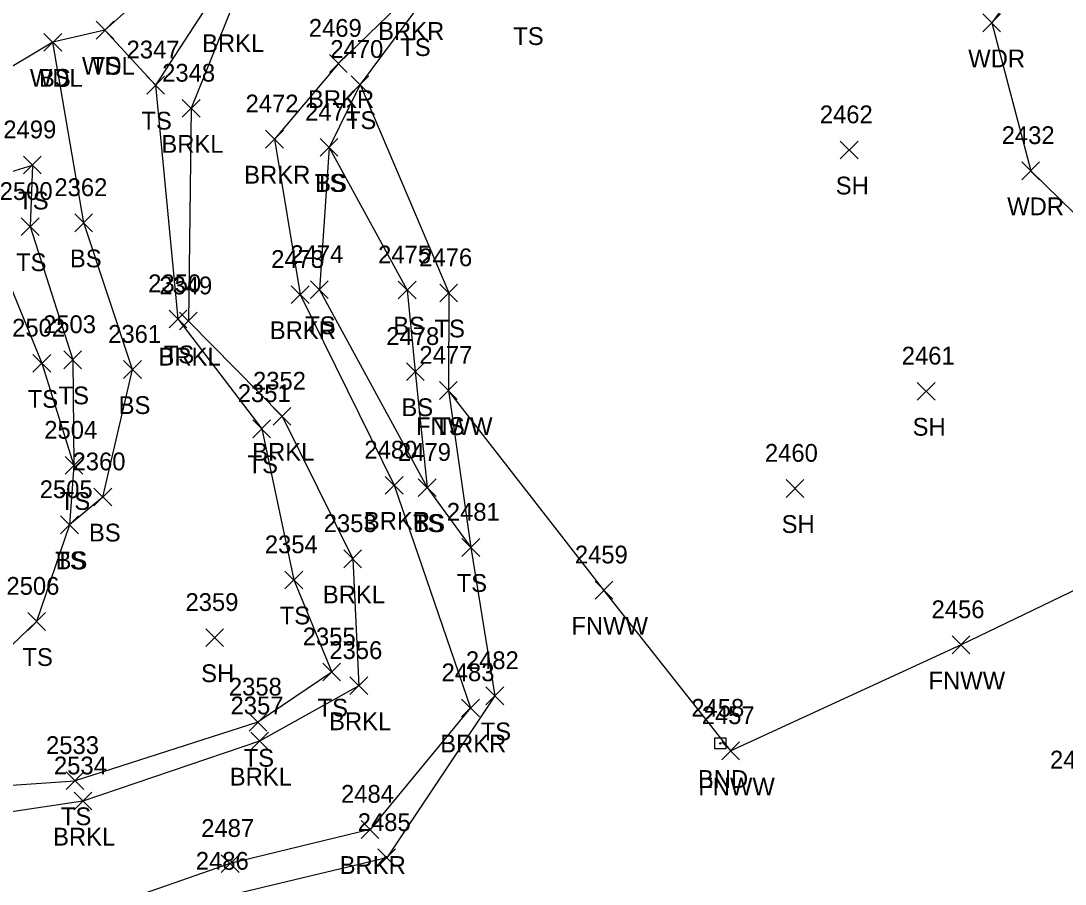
# Model space of a CAD drawing. Extents: x 1505656 to 1508446, y 700805 to 703031.
# Drawn here: x 1506706.6 to 1506823.9, y 702094.5 to 702191.5 of the extents above; entities that cross this region are included whole.
import ezdxf

# ---------------------------------------------------------------- set-up
doc = ezdxf.new("R2010")
doc.units = 0
for name, color, linetype in [('L_A', 7, 'Continuous'), ('L_I', 7, 'Continuous'), ('L_TIC', 7, 'Continuous'), ('LAWA', 7, 'Continuous'), ('LAWE', 7, 'Continuous'), ('LELB', 7, 'Continuous'), ('Level 18', 7, 'Continuous'), ('LFNC', 7, 'Continuous'), ('M_A', 7, 'Continuous'), ('M_I', 7, 'Continuous')]:
    doc.layers.add(name, color=color, linetype=linetype)

msp = doc.modelspace()

# ---------------------------------------------------------------- linework, layer by layer
at = {"layer": 'L_TIC'}
for points in [[(1506814.67, 702190.31), (1506816.67, 702192.31)], [(1506816.67, 702190.31), (1506814.67, 702192.31)], [(1506715.01, 702189.48), (1506717.01, 702191.48)], [(1506717.01, 702189.48), (1506715.01, 702191.48)], [(1506715.01, 702189.48), (1506717.01, 702191.48)], [(1506717.01, 702189.48), (1506715.01, 702191.48)], [(1506709.15, 702188.12), (1506711.15, 702190.12)], [(1506711.15, 702188.12), (1506709.15, 702190.12)], [(1506709.15, 702188.12), (1506711.15, 702190.12)], [(1506711.15, 702188.12), (1506709.15, 702190.12)], [(1506741.24, 702185.74), (1506743.24, 702187.74)], [(1506743.24, 702185.74), (1506741.24, 702187.74)], [(1506720.7, 702183.31), (1506722.7, 702185.31)], [(1506722.7, 702183.31), (1506720.7, 702185.31)], [(1506720.7, 702183.31), (1506722.7, 702185.31)], [(1506722.7, 702183.31), (1506720.7, 702185.31)], [(1506743.68, 702183.37), (1506745.68, 702185.37)], [(1506745.68, 702183.37), (1506743.68, 702185.37)], [(1506743.68, 702183.37), (1506745.68, 702185.37)], [(1506745.68, 702183.37), (1506743.68, 702185.37)], [(1506724.7, 702180.7), (1506726.7, 702182.7)], [(1506726.7, 702180.7), (1506724.7, 702182.7)], [(1506734.07, 702177.24), (1506736.07, 702179.24)], [(1506736.07, 702177.24), (1506734.07, 702179.24)], [(1506740.2, 702176.31), (1506742.2, 702178.31)], [(1506742.2, 702176.31), (1506740.2, 702178.31)], [(1506740.2, 702176.31), (1506742.2, 702178.31)], [(1506742.2, 702176.31), (1506740.2, 702178.31)], [(1506798.65, 702176.02), (1506800.65, 702178.02)], [(1506800.65, 702176.02), (1506798.65, 702178.02)], [(1506706.86, 702174.33), (1506708.86, 702176.33)], [(1506708.86, 702174.33), (1506706.86, 702176.33)], [(1506819.05, 702173.68), (1506821.05, 702175.68)], [(1506821.05, 702173.68), (1506819.05, 702175.68)], [(1506712.63, 702167.83), (1506714.63, 702169.83)], [(1506714.63, 702167.83), (1506712.63, 702169.83)], [(1506706.61, 702167.4), (1506708.61, 702169.4)], [(1506708.61, 702167.4), (1506706.61, 702169.4)], [(1506736.95, 702159.76), (1506738.95, 702161.76)], [(1506738.95, 702159.76), (1506736.95, 702161.76)], [(1506739.11, 702160.31), (1506741.11, 702162.31)], [(1506741.11, 702160.31), (1506739.11, 702162.31)], [(1506748.97, 702160.27), (1506750.97, 702162.27)], [(1506750.97, 702160.27), (1506748.97, 702162.27)], [(1506753.64, 702159.95), (1506755.64, 702161.95)], [(1506755.64, 702159.95), (1506753.64, 702161.95)], [(1506723.22, 702157.03), (1506725.22, 702159.03)], [(1506725.22, 702157.03), (1506723.22, 702159.03)], [(1506724.39, 702156.79), (1506726.39, 702158.79)], [(1506726.39, 702156.79), (1506724.39, 702158.79)], [(1506711.39, 702152.43), (1506713.39, 702154.43)], [(1506713.39, 702152.43), (1506711.39, 702154.43)], [(1506707.92, 702152.04), (1506709.92, 702154.04)], [(1506709.92, 702152.04), (1506707.92, 702154.04)], [(1506718.11, 702151.34), (1506720.11, 702153.34)], [(1506720.11, 702151.34), (1506718.11, 702153.34)], [(1506749.89, 702151.1), (1506751.89, 702153.1)], [(1506751.89, 702151.1), (1506749.89, 702153.1)], [(1506753.61, 702148.98), (1506755.61, 702150.98)], [(1506755.61, 702148.98), (1506753.61, 702150.98)], [(1506753.61, 702148.98), (1506755.61, 702150.98)], [(1506755.61, 702148.98), (1506753.61, 702150.98)], [(1506807.3, 702148.9), (1506809.3, 702150.9)], [(1506809.3, 702148.9), (1506807.3, 702150.9)], [(1506734.91, 702146.08), (1506736.91, 702148.08)], [(1506736.91, 702146.08), (1506734.91, 702148.08)], [(1506732.63, 702144.68), (1506734.63, 702146.68)], [(1506734.63, 702144.68), (1506732.63, 702146.68)], [(1506711.53, 702140.56), (1506713.53, 702142.56)], [(1506713.53, 702140.56), (1506711.53, 702142.56)], [(1506711.53, 702140.56), (1506713.53, 702142.56)], [(1506713.53, 702140.56), (1506711.53, 702142.56)], [(1506747.52, 702138.33), (1506749.52, 702140.33)], [(1506749.52, 702138.33), (1506747.52, 702140.33)], [(1506714.77, 702137.01), (1506716.77, 702139.01)], [(1506716.77, 702137.01), (1506714.77, 702139.01)], [(1506714.77, 702137.01), (1506716.77, 702139.01)], [(1506716.77, 702137.01), (1506714.77, 702139.01)], [(1506751.22, 702138.07), (1506753.22, 702140.07)], [(1506753.22, 702138.07), (1506751.22, 702140.07)], [(1506751.22, 702138.07), (1506753.22, 702140.07)], [(1506753.22, 702138.07), (1506751.22, 702140.07)], [(1506792.57, 702137.97), (1506794.57, 702139.97)], [(1506794.57, 702137.97), (1506792.57, 702139.97)], [(1506711.02, 702133.88), (1506713.02, 702135.88)], [(1506713.02, 702133.88), (1506711.02, 702135.88)], [(1506711.02, 702133.88), (1506713.02, 702135.88)], [(1506713.02, 702133.88), (1506711.02, 702135.88)], [(1506756.13, 702131.34), (1506758.13, 702133.34)], [(1506758.13, 702131.34), (1506756.13, 702133.34)], [(1506756.13, 702131.34), (1506758.13, 702133.34)], [(1506758.13, 702131.34), (1506756.13, 702133.34)], [(1506742.86, 702130.06), (1506744.86, 702132.06)], [(1506744.86, 702130.06), (1506742.86, 702132.06)], [(1506736.24, 702127.69), (1506738.24, 702129.69)], [(1506738.24, 702127.69), (1506736.24, 702129.69)], [(1506771.09, 702126.54), (1506773.09, 702128.54)], [(1506773.09, 702126.54), (1506771.09, 702128.54)], [(1506707.33, 702123.02), (1506709.33, 702125.02)], [(1506709.33, 702123.02), (1506707.33, 702125.02)], [(1506727.33, 702121.2), (1506729.33, 702123.2)], [(1506729.33, 702121.2), (1506727.33, 702123.2)], [(1506811.22, 702120.39), (1506813.22, 702122.39)], [(1506813.22, 702120.39), (1506811.22, 702122.39)], [(1506740.5, 702117.33), (1506742.5, 702119.33)], [(1506742.5, 702117.33), (1506740.5, 702119.33)], [(1506743.55, 702115.8), (1506745.55, 702117.8)], [(1506745.55, 702115.8), (1506743.55, 702117.8)], [(1506758.83, 702114.66), (1506760.83, 702116.66)], [(1506760.83, 702114.66), (1506758.83, 702116.66)], [(1506756.1, 702113.3), (1506758.1, 702115.3)], [(1506758.1, 702113.3), (1506756.1, 702115.3)], [(1506732.2, 702111.69), (1506734.2, 702113.69)], [(1506734.2, 702111.69), (1506732.2, 702113.69)], [(1506732.39, 702109.58), (1506734.39, 702111.58)], [(1506734.39, 702109.58), (1506732.39, 702111.58)], [(1506785.34, 702108.48), (1506787.34, 702110.48)], [(1506787.34, 702108.48), (1506785.34, 702110.48)], [(1506711.65, 702105.12), (1506713.65, 702107.12)], [(1506713.65, 702105.12), (1506711.65, 702107.12)], [(1506711.65, 702105.12), (1506713.65, 702107.12)], [(1506713.65, 702105.12), (1506711.65, 702107.12)], [(1506712.54, 702102.83), (1506714.54, 702104.83)], [(1506714.54, 702102.83), (1506712.54, 702104.83)], [(1506744.8, 702099.64), (1506746.8, 702101.64)], [(1506746.8, 702099.64), (1506744.8, 702101.64)], [(1506746.68, 702096.46), (1506748.68, 702098.46)], [(1506748.68, 702096.46), (1506746.68, 702098.46)], [(1506729.09, 702095.8), (1506731.09, 702097.8)], [(1506731.09, 702095.8), (1506729.09, 702097.8)]]:
    msp.add_lwpolyline(points, dxfattribs=at)
at = {"layer": 'LAWA'}
for points in [[(1506796.06, 702265.39), (1506787.79, 702251.11), (1506771.49, 702234.02), (1506750.3, 702215.14), (1506736.62, 702210.68), (1506727.11, 702200.47), (1506716.01, 702190.48), (1506710.15, 702189.12), (1506695.53, 702180.42), (1506682.85, 702170.87), (1506674.47, 702164.71), (1506646.45, 702141.69), (1506617.58, 702111.72), (1506588.06, 702090.95)], [(1506864.28, 702236.85), (1506836.1, 702219.53), (1506815.67, 702191.31), (1506820.05, 702174.68), (1506845.9, 702149.42), (1506851.82, 702140.45), (1506862.65, 702106.21), (1506869.7, 702082.79), (1506856.8, 702060.43)]]:
    msp.add_lwpolyline(points, dxfattribs=at)
at = {"layer": 'LAWE'}
for points in [[(1506825.4, 702282.02), (1506819.38, 702276.37), (1506817.17, 702263.82), (1506818.81, 702256.36), (1506798.1, 702239.3), (1506775.36, 702221.6), (1506756.52, 702209.5), (1506745, 702199.65), (1506730.28, 702193.02), (1506725.7, 702181.7), (1506725.39, 702157.79), (1506735.91, 702147.08), (1506743.86, 702131.06), (1506744.55, 702116.8), (1506733.39, 702110.58), (1506713.54, 702103.83), (1506688.77, 702100.12), (1506686.8, 702100.19), (1506661.63, 702092.84)], [(1506825.74, 702246.95), (1506813.3, 702234.51), (1506801.33, 702227.81), (1506780.18, 702206.33), (1506761.74, 702197.95), (1506750.12, 702194.39), (1506742.24, 702186.74), (1506735.07, 702178.24), (1506737.95, 702160.76), (1506748.52, 702139.33), (1506757.1, 702114.3), (1506745.8, 702100.64), (1506730.09, 702096.8), (1506703.01, 702087.37)]]:
    msp.add_lwpolyline(points, dxfattribs=at)
at = {"layer": 'LELB'}
for points in [[(1506812.84, 702276.84), (1506812.48, 702261.87), (1506814.97, 702259.43), (1506816.19, 702257.19), (1506796, 702240.07), (1506753.15, 702212.3), (1506739.13, 702204.45), (1506729.76, 702196.69), (1506721.7, 702184.31), (1506724.22, 702158.03), (1506733.63, 702145.68), (1506737.24, 702128.69), (1506741.5, 702118.33), (1506733.2, 702112.69), (1506712.65, 702106.12)], [(1506827.41, 702245.9), (1506813.55, 702232.47), (1506802.49, 702226.49), (1506782.82, 702203.08), (1506763.49, 702193.82), (1506750.79, 702192.58), (1506744.68, 702184.37), (1506741.2, 702177.31), (1506740.11, 702161.31), (1506752.22, 702139.07), (1506757.13, 702132.34), (1506759.83, 702115.66), (1506747.68, 702097.46), (1506729.54, 702093.11)], [(1506716.01, 702190.48), (1506721.7, 702184.31)], [(1506715.77, 702138.01), (1506719.11, 702152.34), (1506713.63, 702168.83), (1506710.15, 702189.12)], [(1506744.68, 702184.37), (1506754.64, 702160.95), (1506754.61, 702149.98), (1506757.13, 702132.34)], [(1506698.28, 702178.41), (1506701.99, 702173.52), (1506703.34, 702166.6), (1506708.92, 702153.04), (1506712.53, 702141.56), (1506712.02, 702134.88), (1506708.33, 702124.02), (1506694.39, 702110.68), (1506690.21, 702106.95), (1506691.8, 702104.68), (1506712.65, 702106.12)], [(1506741.2, 702177.31), (1506749.97, 702161.27), (1506750.89, 702152.1), (1506752.22, 702139.07)], [(1506701.99, 702173.52), (1506707.86, 702175.33), (1506707.61, 702168.4), (1506712.39, 702153.43), (1506712.53, 702141.56)], [(1506715.77, 702138.01), (1506712.02, 702134.88)]]:
    msp.add_lwpolyline(points, dxfattribs=at)
at = {"layer": 'Level 18'}
msp.add_lwpolyline([(1506784.54, 702110.94), (1506785.79, 702110.94), (1506785.79, 702109.69), (1506784.54, 702109.69)], close=True, dxfattribs=at)
msp.add_circle((1506785.16, 702110.31), 0.0833, dxfattribs=at)
at = {"layer": 'LFNC'}
msp.add_lwpolyline([(1507015.48, 702220.45), (1507000.25, 702213.6), (1506981.11, 702204.06), (1506942.05, 702184.41), (1506930.7, 702179.18), (1506921.92, 702174.7), (1506891.87, 702159.82), (1506879.46, 702153.87), (1506851.82, 702140.45), (1506812.22, 702121.39), (1506786.34, 702109.48), (1506772.09, 702127.54), (1506754.61, 702149.98)], dxfattribs=at)

# ---------------------------------------------------------------- texts
at = {"layer": 'L_A'}
for s, p in [('BRKR', (1506746.71, 702189.39)), ('TS', (1506761.9, 702188.82)), ('BRKL', (1506726.93, 702188.02)), ('TS', (1506749.2, 702187.58)), ('WDR', (1506813.03, 702186.31)), ('WDL', (1506713.43, 702185.48)), ('TS', (1506714.42, 702185.48)), ('WDL', (1506707.57, 702184.12)), ('BS', (1506708.59, 702184.12)), ('BRKR', (1506738.83, 702181.74)), ('TS', (1506720.11, 702179.31)), ('TS', (1506720.11, 702179.31)), ('TS', (1506743.09, 702179.37)), ('TS', (1506743.09, 702179.37)), ('BRKL', (1506722.35, 702176.7)), ('BRKR', (1506731.66, 702173.24)), ('TS', (1506739.61, 702172.31)), ('BS', (1506739.64, 702172.31)), ('SH', (1506798.14, 702172.02)), ('TS', (1506706.27, 702170.33)), ('WDR', (1506817.41, 702169.68)), ('TS', (1506706.02, 702163.4)), ('BS', (1506712.07, 702163.83)), ('BRKR', (1506734.54, 702155.76)), ('TS', (1506738.52, 702156.31)), ('BS', (1506748.41, 702156.27)), ('TS', (1506753.05, 702155.95)), ('BRKL', (1506722.03, 702152.79)), ('TS', (1506722.63, 702153.03)), ('TS', (1506707.33, 702148.04)), ('TS', (1506710.8, 702148.43)), ('BS', (1506717.55, 702147.34)), ('BS', (1506749.33, 702147.1)), ('FNWW', (1506750.96, 702144.98)), ('TS', (1506753.02, 702144.98)), ('SH', (1506806.78, 702144.9)), ('BRKL', (1506732.56, 702142.08)), ('TS', (1506732.04, 702140.68)), ('TS', (1506710.94, 702136.56)), ('TS', (1506710.94, 702136.56)), ('BRKR', (1506745.11, 702134.33)), ('TS', (1506750.63, 702134.07)), ('BS', (1506750.66, 702134.07)), ('SH', (1506792.06, 702133.97)), ('BS', (1506714.21, 702133.01)), ('BS', (1506714.21, 702133.01)), ('TS', (1506710.42, 702129.88)), ('BS', (1506710.46, 702129.88)), ('TS', (1506755.54, 702127.34)), ('TS', (1506755.54, 702127.34)), ('BRKL', (1506740.5, 702126.06)), ('TS', (1506735.65, 702123.69)), ('FNWW', (1506768.43, 702122.54)), ('TS', (1506706.74, 702119.02)), ('SH', (1506726.82, 702117.2)), ('FNWW', (1506808.57, 702116.39)), ('TS', (1506739.91, 702113.33)), ('BRKL', (1506741.2, 702111.8)), ('TS', (1506758.24, 702110.66)), ('BRKR', (1506753.69, 702109.3)), ('TS', (1506731.6, 702107.69)), ('BRKL', (1506730.04, 702105.58)), ('FNWW', (1506782.69, 702104.48)), ('TS', (1506711.06, 702101.12)), ('TS', (1506711.06, 702101.12)), ('BRKL', (1506710.18, 702098.83)), ('BRKR', (1506742.39, 702095.64))]:
    msp.add_text(s, height=2, dxfattribs=at).set_placement(p)
at = {"layer": 'L_I'}
for s, p in [('2469', (1506738.92, 702189.74)), ('2470', (1506741.34, 702187.37)), ('2470', (1506741.34, 702187.37)), ('2347', (1506718.44, 702187.31)), ('2347', (1506718.44, 702187.31)), ('2348', (1506722.44, 702184.7)), ('2472', (1506731.81, 702181.24)), ('2471', (1506738.51, 702180.31)), ('2471', (1506738.51, 702180.31)), ('2462', (1506796.35, 702180.02)), ('2499', (1506704.59, 702178.33)), ('2432', (1506816.79, 702177.68)), ('2500', (1506704.18, 702171.4)), ('2362', (1506710.33, 702171.83)), ('2474', (1506736.85, 702164.31)), ('2475', (1506746.71, 702164.27)), ('2476', (1506751.33, 702163.95)), ('2473', (1506734.69, 702163.76)), ('2350', (1506720.87, 702161.03)), ('2349', (1506722.12, 702160.79)), ('2502', (1506705.58, 702156.04)), ('2503', (1506709.05, 702156.43)), ('2361', (1506716.37, 702155.34)), ('2478', (1506747.63, 702155.1)), ('2477', (1506751.35, 702152.98)), ('2477', (1506751.35, 702152.98)), ('2461', (1506805.56, 702152.9)), ('2352', (1506732.65, 702150.08)), ('2351', (1506730.94, 702148.68)), ('2504', (1506709.19, 702144.56)), ('2504', (1506709.19, 702144.56)), ('2480', (1506745.17, 702142.33)), ('2479', (1506748.95, 702142.07)), ('2479', (1506748.95, 702142.07)), ('2460', (1506790.18, 702141.97)), ('2360', (1506712.37, 702141.01)), ('2360', (1506712.37, 702141.01)), ('2505', (1506708.68, 702137.88)), ('2505', (1506708.68, 702137.88)), ('2481', (1506754.43, 702135.34)), ('2481', (1506754.43, 702135.34)), ('2353', (1506740.6, 702134.06)), ('2354', (1506733.98, 702131.69)), ('2459', (1506768.82, 702130.54)), ('2506', (1506704.94, 702127.02)), ('2359', (1506725.06, 702125.2)), ('2456', (1506808.91, 702124.39)), ('2355', (1506738.24, 702121.33)), ('2356', (1506741.23, 702119.8)), ('2482', (1506756.57, 702118.66)), ('2483', (1506753.84, 702117.3)), ('2358', (1506729.94, 702115.69)), ('2357', (1506730.13, 702113.58)), ('2457', (1506783.08, 702112.48)), ('2533', (1506709.39, 702109.12)), ('2533', (1506709.39, 702109.12)), ('2534', (1506710.28, 702106.83)), ('2455', (1506822.22, 702107.49)), ('2484', (1506742.54, 702103.64)), ('2487', (1506726.83, 702099.8)), ('2485', (1506744.42, 702100.46)), ('2486', (1506726.22, 702096.11))]:
    msp.add_text(s, height=2, dxfattribs=at).set_placement(p)
at = {"layer": 'M_A'}
msp.add_text('BND', height=2, dxfattribs=at).set_placement((1506782.65, 702105.31))
at = {"layer": 'M_I'}
msp.add_text('2458', height=2, dxfattribs=at).set_placement((1506781.91, 702113.31))

doc.saveas('drawing.dxf')
